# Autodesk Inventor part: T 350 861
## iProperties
Company: Mayer & Müller AG Schaltgeräte
Created: 2005-12
Part Number: T 350 861
Material: 2.0060.30
Description: DC - Hauptkontakt
Document SubType Name: Modeling
Designer: I.Baliuc
Manufacturer: Standard
Standards Organization: Custom
Density: 8.94 g/cm^3
Zweck: HSLT u. 4000 A (mitte)
Author: T.Messerschmitt
Revision Number: 350861
Keywords: 382072
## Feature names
1. Extrusion2
2. Bohrung_Ø10.1 [Hole]
3. Bohrung_M8_01 [Hole]
4. Extrusion3
5. Extrusion4
6. Rundung4 [Fillet]
7. Bohrung_Ø6.2 [Hole]
8. Extrusion5
9. Extrusion6
10. Spiegeln1 [Mirror]
11. Bohrung_M8_02 [Hole]
12. Extrusion7
